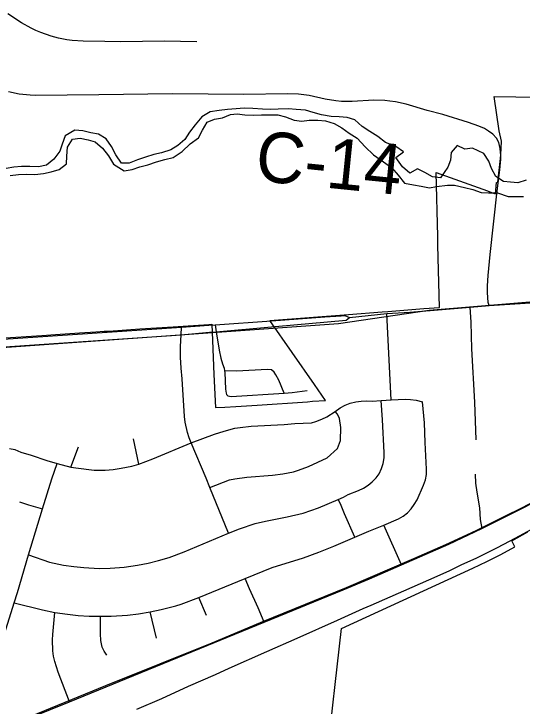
# Model space of a CAD drawing. Extents: x 114604 to 551442, y 316898 to 567001.
# Drawn here: x 124254 to 127278, y 377982 to 382101 of the extents above; entities that cross this region are included whole.
import ezdxf

# ---------------------------------------------------------------- set-up
doc = ezdxf.new("R2010")
doc.units = 0
for name, color, linetype in [('_CIVIL_CONSTRUCTION', 7, 'Continuous'), ('DV_X_County_Line', 7, 'Continuous'), ('GE_P_Alignment_1000_Bearings', 7, 'Continuous'), ('GE_P_Alignment_1000_Cardinal_Points', 7, 'Continuous'), ('GE_P_Alignment_1000_Stations', 7, 'Continuous'), ('GE_P_Alignment_100_Cardinal_Points', 7, 'Continuous'), ('GE_P_Alignment_100_Stations', 7, 'Continuous'), ('GE_P_Alignment_500_Bearings', 7, 'Continuous'), ('PM_P_CL_Double_Solid', 7, 'Continuous')]:
    doc.layers.add(name, color=color, linetype=linetype)

msp = doc.modelspace()

# ---------------------------------------------------------------- linework, layer by layer
at = {"layer": '_CIVIL_CONSTRUCTION'}
msp.add_lwpolyline([(123404.8, 377528.5), (124018.8, 377778.9), (124584.7, 378008), (125744, 378481.1), (126213.3, 378673), (126370.3, 378739.6), (126560.4, 378822.6), (126842.2, 378945.3), (127039.1, 379037.8), (127584.8, 379311.8), (127800.8, 379422.3), (127833.1, 379439.7)], dxfattribs=at)
at = {"layer": 'DV_X_County_Line'}
for points in [[(126526, 381312.3), (126466.1, 381334.4), (126420.1, 381370.5), (126372.2, 381400.6), (126326.2, 381430.6), (126282.3, 381470.7), (126238.3, 381484.8), (126190.3, 381488.8), (126142.4, 381490.8), (126084.4, 381498.9), (126034.4, 381512.9), (125990.5, 381527), (125934.5, 381531), (125888.5, 381535), (125826.6, 381533), (125780.6, 381531), (125734.6, 381533.1), (125676.7, 381537.1), (125624.7, 381539.1), (125576.7, 381535.1), (125524.7, 381531.1), (125476.7, 381525.2), (125422.8, 381517.2), (125372.8, 381487.1), (125332.8, 381441.1), (125298.7, 381397), (125270.7, 381352.9), (125230.7, 381316.8), (125188.7, 381290.8), (125132.7, 381272.8), (125086.7, 381264.8), (125036.8, 381248.8), (124990.8, 381232.8), (124940.8, 381212.8), (124894.8, 381212.8), (124860.9, 381260.9), (124834.9, 381311), (124803, 381357.1), (124759, 381385.2), (124713, 381393.2), (124665.1, 381405.2), (124617.1, 381409.3), (124559.1, 381375.2), (124541.1, 381325.1), (124527, 381283.1), (124493, 381237), (124449, 381201), (124401, 381191), (124349.1, 381193), (124299.1, 381193), (124255.1, 381189), (124209.1, 381181)], [(124233.1, 381138.9), (124281.1, 381144.9), (124327, 381146.9), (124379, 381144.9), (124431, 381150.9), (124477, 381160.9), (124525, 381174.9), (124567, 381208.9), (124569, 381253), (124573, 381307.1), (124603.1, 381355.2), (124649, 381361.2), (124697, 381351.1), (124739, 381339.1), (124780.9, 381301), (124816.9, 381254.9), (124846.8, 381206.8), (124910.8, 381166.7), (124958.7, 381174.7), (125004.7, 381190.7), (125050.7, 381202.7), (125102.7, 381220.7), (125152.7, 381234.7), (125202.7, 381246.7), (125256.7, 381280.8), (125302.7, 381326.8), (125352.7, 381362.9), (125376.7, 381409), (125404.7, 381457), (125448.7, 381473.1), (125496.7, 381481.1), (125542.7, 381501.1), (125582.7, 381505.1), (125628.6, 381499), (125682.6, 381497), (125728.6, 381499), (125824.5, 381499), (125870.5, 381488.9), (125922.5, 381468.9), (125968.4, 381462.8), (126010.4, 381468.8), (126062.4, 381468.8), (126108.4, 381464.8), (126160.3, 381448.7), (126206.3, 381422.7), (126250.2, 381390.6), (126296.2, 381360.5), (126344.1, 381310.4), (126394, 381262.3), (126454, 381220.2), (126503.9, 381184.1), (126539.9, 381140)], [(127301.4, 381111.7), (127253.4, 381095.7), (127209.5, 381099.7), (127167.5, 381103.7), (127121.5, 381133.8), (127095.6, 381179.9), (127079.6, 381224), (127049.7, 381270.1), (126983.8, 381302.1), (126937.8, 381296.2), (126891.8, 381318.2), (126855.8, 381276.1), (126851.8, 381230), (126835.7, 381188), (126791.7, 381125.9), (126745.8, 381131.9), (126699.8, 381156), (126655.8, 381178), (126609.8, 381152), (126565.9, 381190.1), (126526, 381246.2), (126572, 381280.3), (126526, 381312.3)], [(126539.9, 381140), (126577.8, 381093.9), (126631.8, 381083.9), (126677.7, 381075.8), (126727.7, 381065.8), (126769.7, 381073.8), (126833.7, 381081.8), (126875.6, 381081.8), (126935.6, 381067.7), (126985.6, 381055.7), (127035.5, 381037.6), (127077.5, 381035.6), (127131.5, 381035.6), (127195.4, 381013.5), (127287.4, 381013.5)]]:
    msp.add_lwpolyline(points, dxfattribs=at)
at = {"layer": 'GE_P_Alignment_1000_Bearings'}
for points in [[(114843.2, 379479.7), (121181.9, 379901.3), (126186.1, 380258), (126725.6, 380338.5), (128237.3, 380461.9), (129506.6, 380556.5)], [(124986.3, 377962.8), (125133.9, 378027.8), (125294.2, 378099.7), (125454.5, 378170.4), (125535.7, 378206.6), (125758.6, 378306), (125940.4, 378386.7), (126180, 378493.4), (126333.1, 378561.6), (126379.9, 378583), (126574, 378667.2), (126673.4, 378710.5), (126772, 378754.4), (126847.4, 378788.1), (126916.2, 378821.5), (127008.8, 378863.6), (127065.1, 378892), (127131.2, 378925.8), (127203.4, 378962.5), (127262.4, 378994.7), (127349.1, 379042.5)]]:
    msp.add_lwpolyline(points, dxfattribs=at)
at = {"layer": 'GE_P_Alignment_1000_Cardinal_Points'}
msp.add_lwpolyline([(125343.3, 381934.7), (125149.5, 381938.3), (124891.5, 381935), (124794.8, 381935.2), (124667.6, 381937.8), (124601.6, 381942.7), (124569.7, 381946.7), (124520.6, 381955.5), (124475.6, 381967.8), (124415.2, 381989.6), (124386, 382002.4), (124357.1, 382016), (124300.3, 382047.1), (124218.8, 382100.7)], dxfattribs=at)
at = {"layer": 'GE_P_Alignment_1000_Stations'}
for points in [[(126801.7, 380342.1), (126969.4, 380356.4), (127082.9, 380365.2), (127296.5, 380379.5), (127547, 380396.7), (128264.4, 380444.9)], [(126251.1, 380294.9), (126473.7, 380316.8), (126610.1, 380325.9), (126801.7, 380342.1)], [(125788, 380273.2), (126104.3, 380297.9), (126202.3, 380304.1), (126223.8, 380305.1), (126251.1, 380294.9)], [(125809.6, 380240.4), (126231.3, 380277.2), (126251.1, 380294.9)], [(123716.5, 380134.3), (125251.6, 380236.8), (125415.1, 380248.1)], [(125415.1, 380248.1), (125451.6, 380250.5), (125788, 380273.2)], [(125422.8, 380206.3), (125458.4, 380209.5), (125809.6, 380240.4)], [(123705.1, 380085.3), (125249.2, 380191.4), (125417.8, 380205.9), (125422.8, 380206.3)]]:
    msp.add_lwpolyline(points, dxfattribs=at)
at = {"layer": 'GE_P_Alignment_100_Cardinal_Points'}
for p, q in [((126499, 379803.8), (126473.7, 380316.8)), ((125451.6, 380250.5), (125458.4, 380209.5)), ((124998.5, 379421.7), (124966.4, 379572.9)), ((124592.7, 379402.8), (124638.4, 379523.5)), ((126560.4, 378822.6), (126455.9, 379058.9)), ((125401.2, 378521.7), (125354.2, 378628.3)), ((125103.4, 378386.1), (125064.5, 378543.1))]:
    msp.add_line(p, q, dxfattribs=at)
for points in [[(127004.6, 379566.3), (126996, 379789.5), (126979.3, 380107.9), (126974.9, 380267.2), (126969.4, 380356.4)], [(125530.5, 379010.2), (125420.9, 379281.8), (125398.5, 379338.4), (125309.6, 379547.7), (125297.9, 379578), (125288.2, 379609.1), (125273.4, 379672.2), (125269.6, 379704.5), (125255.6, 379929.4), (125249.6, 379993.1), (125245.7, 380057.1), (125245.5, 380121), (125249.2, 380191.4), (125251.6, 380236.8)], [(125458.4, 380209.5), (125476.7, 380098.9), (125486.3, 380051.4), (125495.2, 380018.9), (125505.1, 379991.8), (125507.7, 379977.5)], [(125862, 379843.4), (125830.1, 379921.6), (125813.1, 379953.5), (125802.4, 379969.3), (125787.6, 379981.8), (125763.6, 379984.8), (125579.1, 379973.8), (125507.7, 379977.5)], [(125507.7, 379977.5), (125509.6, 379967.2), (125513.9, 379867.8), (125517.6, 379843.3), (125520.3, 379835.4), (125527.3, 379827.5), (125547.6, 379824.1), (125862, 379843.4)], [(125862, 379843.4), (125910.6, 379847.8), (126000.2, 379859.9)], [(124228, 379514.8), (124259.4, 379508.5), (124295.8, 379492.3), (124358.1, 379474.1), (124450.5, 379443.4), (124512.5, 379424.8), (124592.7, 379402.8), (124700.5, 379388.7), (124732.7, 379386.2), (124797.3, 379386.2), (124845.4, 379390.1), (124893.6, 379396.6), (124957.3, 379409.9), (124998.5, 379421.7), (125080.6, 379452.7), (125309.6, 379547.7), (125449.1, 379600), (125505.9, 379618.1), (125568.9, 379635.1), (125601.2, 379640.1), (125666.2, 379646.6), (125861.7, 379657.5), (125926.7, 379663.6), (126024.5, 379667.9), (126050.7, 379674.5), (126086.5, 379688.1), (126115.9, 379702.3), (126165.2, 379735.5), (126196.6, 379757.1), (126225.7, 379772.6), (126256.2, 379784.3), (126288.2, 379791.9), (126320.7, 379796.1), (126353.3, 379797.6), (126386.1, 379796.3), (126440.6, 379800.6), (126499, 379803.8), (126582.1, 379807.5), (126615, 379806.4), (126647.4, 379802.2), (126684.9, 379792.5)], [(124256.1, 378595.8), (124425.1, 378553.7), (124498, 378539.6), (124572.7, 378528.5), (124638, 378521.7), (124702.8, 378517.7), (124770.9, 378516.3), (124833.2, 378517.5), (124930.7, 378523.5), (124995.6, 378531.1), (125064.5, 378543.1), (125131.2, 378557.4), (125217.9, 378579.3), (125249.2, 378588.8), (125354.2, 378628.3), (125631.5, 378742), (125791.7, 378806.1), (125977, 378864.9), (126068.6, 378897.2), (126158.3, 378932.5), (126283.8, 378987.2), (126365.4, 379022.8), (126455.9, 379058.9), (126543.7, 379096.6), (126571.4, 379112.4), (126597.2, 379132.1), (126618.8, 379154.9), (126636.8, 379180.8), (126653, 379208.2), (126692.4, 379296.4), (126702.5, 379327.4), (126709.2, 379359.4), (126709.6, 379392.2), (126700.8, 379549.4), (126698.3, 379667.6), (126684.9, 379792.5)], [(124342.5, 378881.4), (124467.1, 378838.7), (124549.4, 378821), (124610.3, 378812.1), (124671.5, 378805.6), (124762.1, 378801.4), (124826.9, 378802.7), (124910.7, 378809.2), (124989.2, 378819.9), (125053.1, 378832.3), (125115.7, 378848.2), (125177.5, 378866.8), (125267.5, 378900.6), (125530.5, 379010.2), (125597.1, 379036.5), (125689.3, 379067.9), (125752.5, 379082.9), (125879.8, 379108.3), (125974.8, 379129.5), (126066.4, 379161.9), (126183.1, 379211), (126215.2, 379225.2), (126244.1, 379240.1), (126303.9, 379264.1), (126333.6, 379278.3), (126361.4, 379295.5), (126387.1, 379315.8), (126410, 379339.1), (126427.4, 379363.4), (126442.5, 379394.9), (126451.7, 379426.2), (126456.6, 379458.6), (126456.9, 379491), (126447.9, 379686), (126440.6, 379800.6)], [(125420.9, 379281.8), (125536.9, 379327.8), (125568.9, 379334.1), (125641.1, 379343.5), (125793.3, 379354.9), (125855.4, 379363.5), (125918.6, 379376.6), (125948.3, 379384.7), (126007, 379407.9), (126118.4, 379459.6), (126179.9, 379515.3), (126197.3, 379561.7), (126199.1, 379639.2), (126191.5, 379693.2), (126180.7, 379718.6), (126165.2, 379735.5)], [(122583.6, 377504.7), (122897.6, 377633.7), (123164.9, 377742.3), (123331.2, 377810.8), (123423.2, 377846.8), (123721.2, 377968.4), (123912.4, 378043.3), (123934.7, 378053.8), (123962.4, 378070.4), (123986.5, 378092), (124054.3, 378162.7), (124092.9, 378210.1), (124131.7, 378266.4), (124162.8, 378322.5), (124176.3, 378351.6), (124188.5, 378381.3), (124198.5, 378411.8), (124256.1, 378595.8), (124275.6, 378657), (124342.5, 378881.4), (124425.7, 379156.5), (124479.8, 379333.6), (124512.5, 379424.8)], [(126999.1, 379361.2), (127001.8, 379308.3), (127008.6, 379253.9), (127024.2, 379162.3), (127028.7, 379092.9), (127039.1, 379037.8)], [(126283.8, 378987.2), (126221.7, 379125.6), (126197.5, 379185.5), (126183.1, 379211)], [(124288.8, 379196.4), (124341.8, 379178.5), (124425.7, 379156.5)], [(125744, 378481.1), (125707.5, 378565.9), (125655.5, 378679.4), (125631.5, 378742)], [(124584.7, 378008), (124517.2, 378184.6), (124498.5, 378247), (124490.9, 378278.7), (124486.8, 378311), (124484.2, 378375.7), (124485.5, 378407.9), (124498, 378539.6)], [(124807.1, 378285.7), (124791.3, 378308.4), (124780, 378333.1), (124771.1, 378372.6), (124769, 378411.7), (124770.9, 378516.3)]]:
    msp.add_lwpolyline(points, dxfattribs=at)
at = {"layer": 'GE_P_Alignment_100_Stations'}
for points in [[(124172.7, 380170.7), (124421.2, 380187.2), (124502, 380192.5), (124645.5, 380202), (124742.4, 380208.4), (124792.5, 380211.7), (124820.4, 380213.6), (125003.2, 380225.7), (125202.8, 380238.9), (125262.7, 380242.8), (125414, 380252.9), (125431.8, 380254.1), (125436, 380157.1), (125444.7, 379954.5), (125453.2, 379757.9), (125509.2, 379761.2), (125574.3, 379765.2), (125638.8, 379769.1), (125702, 379772.9), (125761.9, 379776.5), (125821.8, 379780.1), (125881.7, 379784.3), (125941.5, 379788.4), (126001.4, 379792.6), (126031.5, 379795.7), (126109.3, 379801.1), (126043.3, 379895.6), (125777.7, 380276.5), (126245.5, 380312.4), (126444.7, 380327.7), (126478.7, 380330.3), (126502.7, 380332.1), (126694.1, 380346.8), (126786.4, 380353.9), (126777.8, 380725), (126776.6, 380776.9), (126766.7, 381156.8), (127071.4, 381047.4), (127095.6, 381038.6), (127120.2, 381029.8), (127126.8, 381097.9), (127134.5, 381098.6), (127150.3, 381239.3), (127151, 381261.6), (127155.4, 381343.9), (127142, 381404.3), (127111.5, 381609), (127501.5, 381603.2)], [(127329, 379187.3), (127259.3, 379152), (127189.6, 379117.3), (127189, 379117), (127054.6, 379050), (127018.4, 379033), (127006.1, 379027.3), (126921.8, 378987.4), (126823.2, 378940.7), (126631.9, 378857.7), (126231.7, 378684.7), (125733.9, 378482.4), (125431.3, 378356.5), (124799.8, 378102.4), (124271.6, 377885.9)], [(126114.6, 377655.1), (126204.3, 378443.7), (126984.1, 378801.8), (127068.8, 378842.1), (127152.4, 378884.7), (127234.8, 378929.7), (127216.8, 378965.9), (127312.7, 379017.8)]]:
    msp.add_lwpolyline(points, dxfattribs=at)
at = {"layer": 'GE_P_Alignment_500_Bearings'}
for points in [[(127138.9, 381334.4), (127125, 381360.1), (127103.5, 381384.3), (127077.8, 381402.9), (127053.8, 381417.6), (127021.1, 381432.9), (126959.9, 381454.3), (126806.3, 381502.5), (126712.9, 381526.5), (126588.3, 381562.3), (126525.5, 381576.5), (126490.6, 381582.1), (126461.4, 381584.7), (126396.8, 381586.2), (126267.8, 381580), (126203.3, 381579.1), (126170.7, 381582.3), (126106.5, 381592.6), (126011.9, 381614), (125947.6, 381622), (125882.6, 381625.3), (125622.8, 381620.8), (125198.9, 381624.7), (124760.5, 381618), (124383.6, 381615.8), (124351.2, 381617.2), (124286.6, 381623.1), (124222.5, 381635.9)], [(127130.3, 381047.7), (127145.2, 381173.4), (127151.5, 381236.5), (127152.2, 381258.8), (127148.6, 381299.7), (127138.9, 381334.4)], [(127082.9, 380365.2), (127076.5, 380384.1), (127072.7, 380442), (127072.4, 380483.3), (127075.5, 380542.9), (127087.5, 380669.3), (127130.3, 381047.7)]]:
    msp.add_lwpolyline(points, dxfattribs=at)

# ---------------------------------------------------------------- texts
at = {"layer": 'PM_P_CL_Double_Solid'}
msp.add_text('C-14', height=300.02, rotation=354.2653, dxfattribs=at).set_placement((125683.4, 381109.4))

doc.saveas('drawing.dxf')
